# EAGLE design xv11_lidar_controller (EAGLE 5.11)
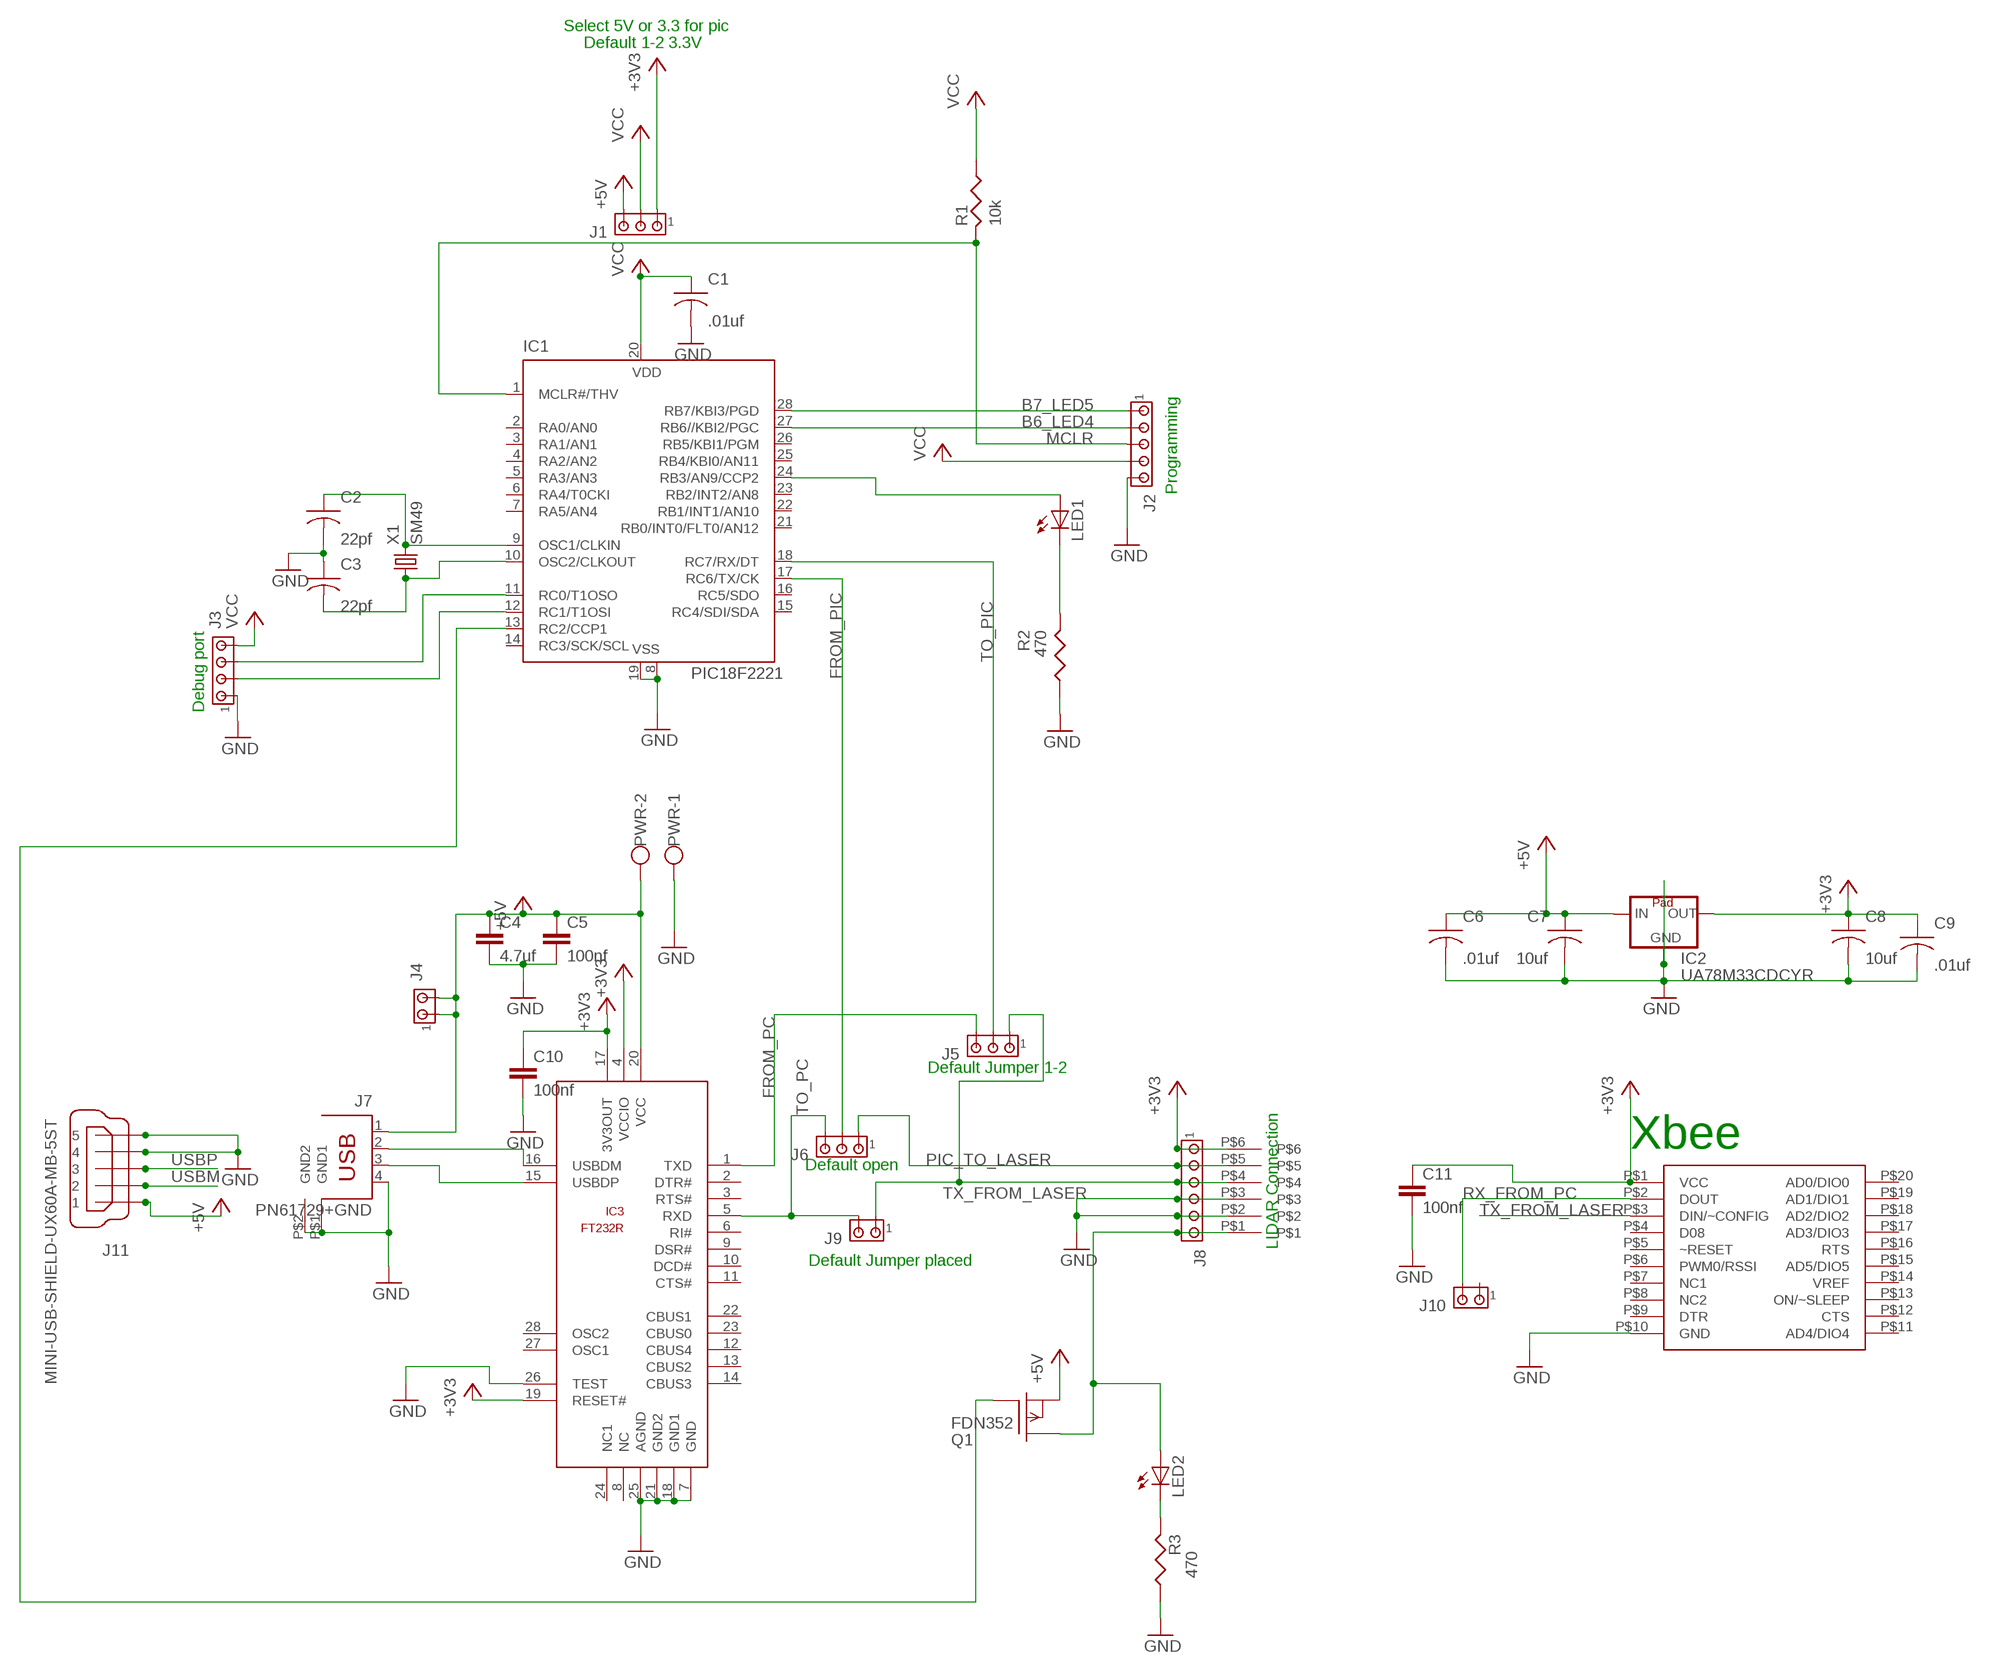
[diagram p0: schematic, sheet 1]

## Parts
C1  .01uf  C805  [C0805]
C2  22pf  C805  [C0805]
C3  22pf  C805  [C0805]
C4  4.7uf  C_805  [C0805]
C5  100nf  C_805  [C0805]
C6  .01uf  C805  [C0805]
C7  10uf  C805  [C0805]
C8  10uf  C805  [C0805]
C9  .01uf  C805  [C0805]
C10  100nf  C_805  [C0805]
C11  100nf  C_805  [C0805]
IC1  PIC18F2221  [SO-28W]
IC2  UA78M33CDCYR  [SOT223]
IC3  FT232R  [SSOP28]
IC4  XBEE  [MAXSTREAMXBEE]
J1  MTA03-100  [10X03MTA]
J2  MTA05-100  [10X05MTA]
J3  MTA04-100  [10X04MTA]
J4  MTA02-100  [10X02MTA]
J5  MTA03-100  [10X03MTA]
J6  MTA03-100  [10X03MTA]
J7  PN61729+GND  [PN61729+GND]
J8  MTA06-100  [10X06MTA]
J9  MTA02-100  [10X02MTA]
J10  MTA02-100  [10X02MTA]
J11  MINI-USB-SHIELD-UX60A-MB-5ST  [UX60A-MB-5ST]
LED1  LEDCHIPLED_0805  [CHIPLED_0805]
LED2  LEDCHIPLED_0805  [CHIPLED_0805]
PWR  Vin  W237-02P  [W237-132]
Q1  FDN352  [SUPERSOT3]
R1  10k  R-805  [R0805]
R2  470  R-805  [R0805]
R3  470  R-805  [R0805]
U$1  HEADER_2MMX6  [HEADER_2MMX6]
X1  SM49  [SM49]

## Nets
+3V3: C8.1 C9.1 C10.1 C11.1 IC2.3(OUT) IC3.4(VCCIO) IC3.17(3V3OUT) IC3.19(RESET#) IC4.P$1(VCC) J1.1 J8.6 U$1.P$6
+5V: C4.1 C5.1 C6.1 C7.1 IC2.1(IN) IC3.20(VCC) J1.3 J4.1 J4.2 J7.1 J11.1 PWR.2 Q1.P$2(S)
B6_LED4: IC1.27(RB6//KBI2/PGC) J2.2
B7_LED5: IC1.28(RB7/KBI3/PGD) J2.1
FROM_PC: IC3.1(TXD) J5.3
FROM_PIC: IC1.17(RC6/TX/CK) J6.2
GND: C1.2 C2.2 C3.1 C4.2 C5.2 C6.2 C7.2 C8.2 C9.2 C10.2 C11.2 IC1.8(VSS) IC1.19(VSS) IC2.2(GND) IC2.4(TAB) IC3.7(GND) IC3.18(GND1) IC3.21(GND2) IC3.25(AGND) IC3.26(TEST) IC4.P$10(GND) J2.5 J3.1 J7.4 J7.P$1(GND1) J7.P$2(GND2) J8.2 J8.3 J11.4 J11.5 PWR.1 R2.1 R3.1 U$1.P$2 U$1.P$3
MCLR: IC1.1(MCLR#/THV) J2.3 R1.2
N$1: IC1.24(RB3/AN9/CCP2) LED1.A
N$2: J8.1 LED2.A Q1.P$3(D) U$1.P$1
N$3: IC1.13(RC2/CCP1) Q1.P$1(G)
N$6: LED1.C R2.2
N$7: LED2.C R3.2
N$9: IC1.12(RC1/T1OSI) J3.2
N$10: IC1.11(RC0/T1OSO) J3.3
OSC: C2.1 IC1.9(OSC1/CLKIN) X1.2
OSC2: C3.2 IC1.10(OSC2/CLKOUT) X1.1
PIC_TO_LASER: J6.1 J8.5 U$1.P$5
RX_FROM_PC: IC4.P$2(DOUT) J10.2
TO_PC: IC3.5(RXD) J6.3 J9.2
TO_PIC: IC1.18(RC7/RX/DT) J5.2
TX_FROM_LASER: IC4.P$3(DIN/~CONFIG) J5.1 J8.4 J9.1 U$1.P$4
USBM: IC3.16(USBDM) J7.2 J11.2
USBP: IC3.15(USBDP) J7.3 J11.3
VCC: C1.1 IC1.20(VDD) J1.2 J2.4 J3.4 R1.1
Unconnected: IC1.2(RA0/AN0) IC1.3(RA1/AN1) IC1.4(RA2/AN2) IC1.5(RA3/AN3) IC1.6(RA4/T0CKI) IC1.7(RA5/AN4) IC1.14(RC3/SCK/SCL) IC1.15(RC4/SDI/SDA) IC1.16(RC5/SDO) IC1.21(RB0/INT0/FLT0/AN12) IC1.22(RB1/INT1/AN10) IC1.23(RB2/INT2/AN8) IC1.25(RB4/KBI0/AN11) IC1.26(RB5/KBI1/PGM) IC3.2(DTR#) IC3.3(RTS#) IC3.6(RI#) IC3.8(NC) IC3.9(DSR#) IC3.10(DCD#) IC3.11(CTS#) IC3.12(CBUS4) IC3.13(CBUS2) IC3.14(CBUS3) IC3.22(CBUS1) IC3.23(CBUS0) IC3.24(NC1) IC3.27(OSC1) IC3.28(OSC2) IC4.P$4(D08) IC4.P$5(~RESET) IC4.P$6(PWM0/RSSI) IC4.P$7(NC1) IC4.P$8(NC2) IC4.P$9(DTR) IC4.P$11(AD4/DIO4) IC4.P$12(CTS) IC4.P$13(ON/~SLEEP) IC4.P$14(VREF) IC4.P$15(AD5/DIO5) IC4.P$16(RTS) IC4.P$17(AD3/DIO3) IC4.P$18(AD2/DIO2) IC4.P$19(AD1/DIO1) IC4.P$20(AD0/DIO0) J10.1 J11.M1(S1) J11.M2(S2) J11.M3(S3) J11.M4(S4)

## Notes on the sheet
- Select 5V or 3.3 for pic
- Default 1-2 3.3V
- Programming
- Debug port
- Default Jumper 1-2
- Xbee
- Default open
- LIDAR Connection
- Default Jumper placed

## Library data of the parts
C1-C3 C6-C9 = Ringo:C805: 805 Cap
C4 C5 C10 C11 = NCR:C_805
IC1 = microchip-2:PIC18F2221
IC2 = Ringo:UA78M33CDCYR
IC3 = NCR:FT232R
IC4 = xbee:XBEE
J1 J5 J6 = con-amp:MTA03-100: AMP connector; OC_FARNELL: unknown; OC_NEWARK: unknown
J2 = con-amp:MTA05-100: AMP connector
J3 = con-amp:MTA04-100: AMP connector; OC_FARNELL: unknown; OC_NEWARK: unknown
J4 J9 J10 = con-amp:MTA02-100: AMP connector
J7 = con-berg:PN61729+GND
J8 = con-amp:MTA06-100: AMP connector
J11 = con-hirose:MINI-USB-SHIELD-: MINI USB Connector Source: http://www.hirose.co.jp/cataloge_hp/e24000019.pdf
LED1 LED2 = led:LED: LED
PWR = con-wago-508:W237-02P: WAGO SREW CLAMP
Q1 = Ringo:FDN352
R1-R3 = Ringo:R-805: 805 Resistor
U$1 = Ringo:HEADER_2MMX6
X1 = Ringo:SM49: ECS-200-20-5P-TR

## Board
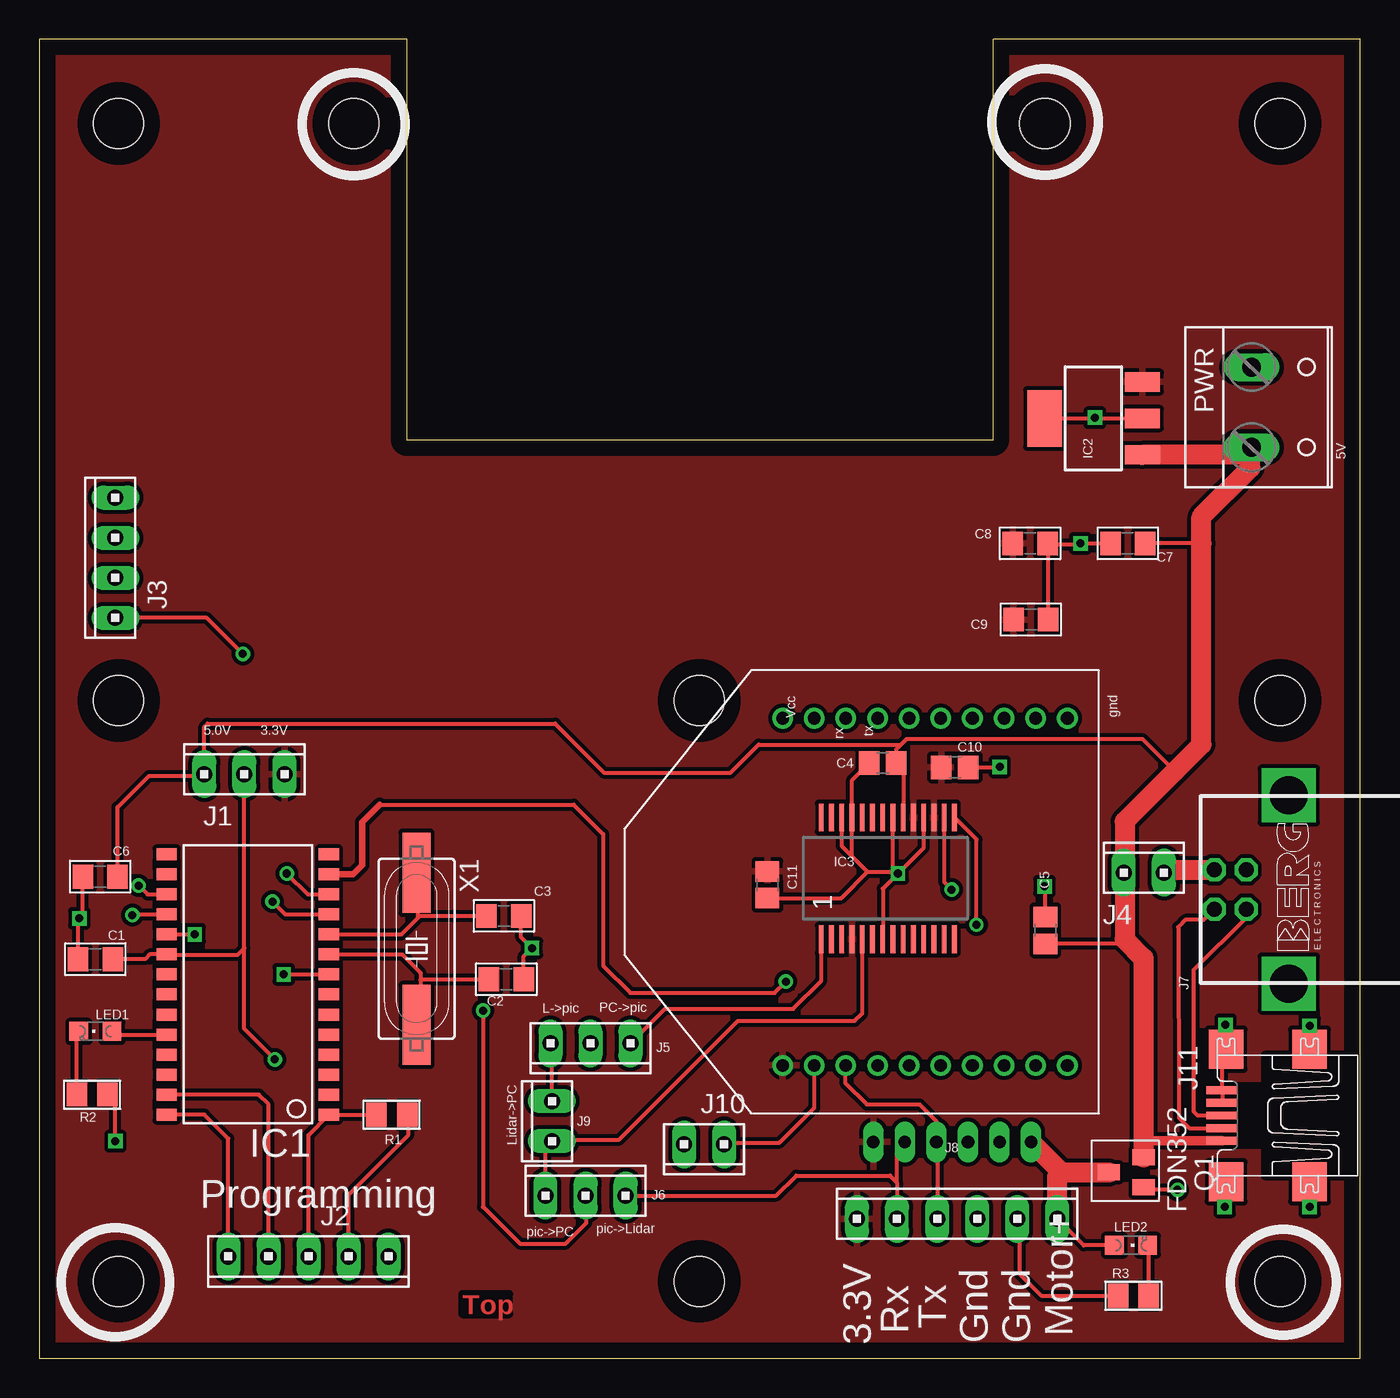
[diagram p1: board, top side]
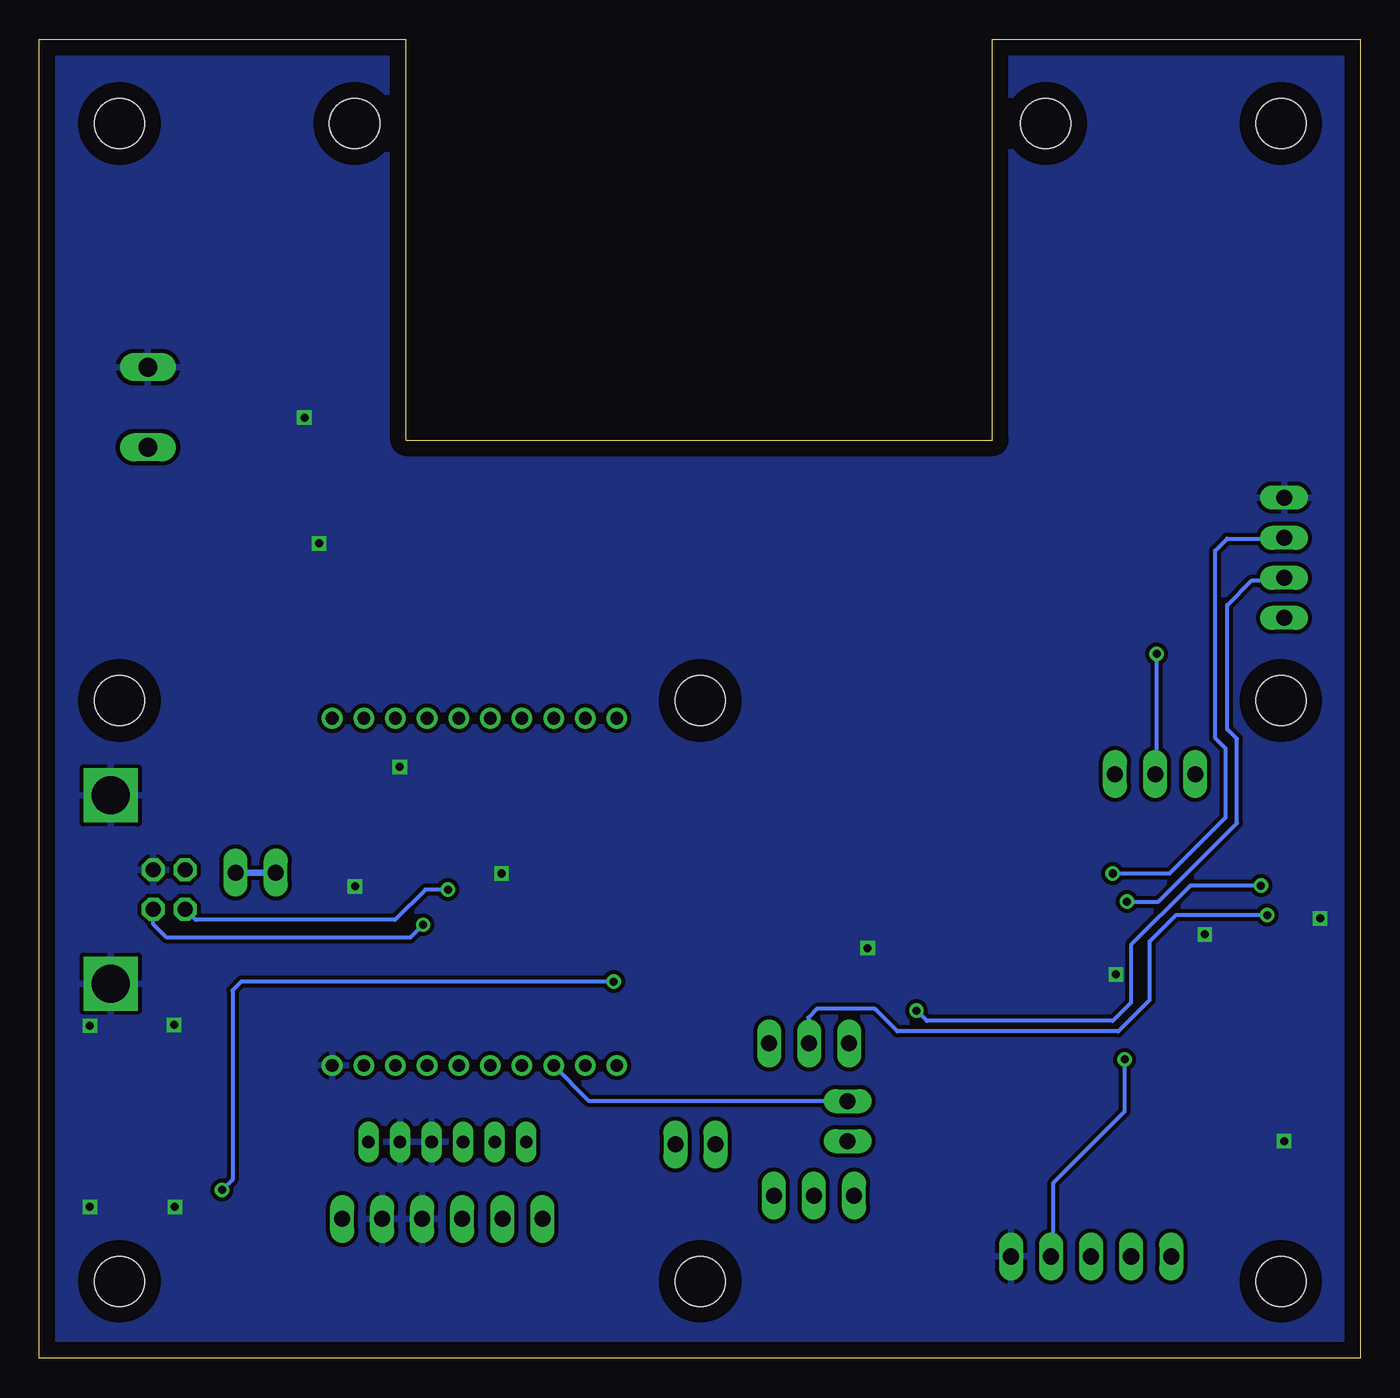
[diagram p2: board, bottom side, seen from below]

Size 83.76 x 83.63 mm. Coordinates in mm from the lower left corner, seen from the top.
Outline: 0,0 83.76,0 83.76,83.63 60.5,83.63 60.5,58.23 23.31,58.23 23.31,83.63 0,83.63 0,0
Copper layers (1+16): Top 0.035mm / dielectric 1.5mm / Bottom 0.035mm
Design rules "default *": minimum track width 8mil, minimum drill 15mil, track to track 8mil, track to pad 8mil, pad to pad 8mil, via to via 8mil, smd to smd 8mil, copper to edge 40mil, drill to drill 8mil, minimum pad ring 10mil, minimum via ring 8mil, stop-mask expansion 4mil, vias tented up to drill 0mil, thermal gap 10mil
Holes 3.17 mm at 5.02,4.89 78.68,4.89 5.02,41.72 19.94,78.3 63.77,78.3 41.85,4.89 78.68,41.72 5.02,78.3 78.68,78.3 41.85,41.72

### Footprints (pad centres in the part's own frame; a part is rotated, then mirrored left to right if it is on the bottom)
C0805 = smd 1.3 x 1.5: 1 -1.104,0; 2 1.104,0
C0805' = smd 1.3 x 1.5: 1 -0.85,0; 2 0.85,0
SO-28W = smd 0.762 x 1.27: 1 -7.62,-5.207; 2 -6.35,-5.207; 3 -5.08,-5.207; 4 -3.81,-5.207; 5 -2.54,-5.207; 6 -1.27,-5.207; 7 0,-5.207; 8 1.27,-5.207; 9 2.54,-5.207; 10 3.81,-5.207; 11 5.08,-5.207; 12 6.35,-5.207; 13 7.62,-5.207; 14 8.89,-5.207; 15 8.89,5.08; 16 7.62,5.08; 17 6.35,5.08; 18 5.08,5.08; 19 3.81,5.08; 20 2.54,5.08; 21 1.27,5.08; 22 0,5.08; 23 -1.27,5.08; 24 -2.54,5.08; 25 -3.81,5.08; 26 -5.08,5.08; 27 -6.35,5.08; 28 -7.62,5.08
SOT223 = smd 1.219 x 2.235: 1 -2.311,-3.099; 2 0,-3.099; 3 2.311,-3.099 | smd 3.6 x 2.2: 4 0,3.099
SSOP28 = smd 0.3 x 1.75: 1 -3.745,-3.865; 2 -3.095,-3.865; 3 -2.445,-3.865; 4 -1.795,-3.865; 5 -1.145,-3.865; 6 -0.495,-3.865; 7 0.155,-3.865; 8 0.805,-3.865; 9 1.455,-3.865; 10 2.105,-3.865; 11 2.755,-3.865; 12 3.405,-3.865; 13 4.055,-3.865; 14 4.705,-3.865; 15 4.705,3.865; 16 4.055,3.865; 17 3.405,3.855; 18 2.755,3.855; 19 2.105,3.855; 20 1.455,3.865; 21 0.805,3.865; 22 0.155,3.865; 23 -0.495,3.865; 24 -1.145,3.865; 25 -1.795,3.855; 26 -2.445,3.855; 27 -3.095,3.855; 28 -3.755,3.855
MAXSTREAMXBEE = drill 0.8 round: P$1 -11,8.026; P$2 -11,6.02; P$3 -11,4.013; P$4 -11,2.007; P$5 -11,0; P$6 -11,-2.007; P$7 -11,-4.013; P$8 -11,-6.02; P$9 -11,-8.026; P$10 -11,-10.033; P$11 11.01,-10.033; P$12 11.01,-8.026; P$13 11.01,-6.02; P$14 11.01,-4.013; P$15 11.01,-2.007; P$16 11.01,0; P$17 11.01,2.007; P$18 11.01,4.013; P$19 11.01,6.02; P$20 11.01,8.026
10X03MTA = drill 1.016 long: 1 2.54,0; 2 0,0; 3 -2.54,0
10X05MTA = drill 1.016 long: 1 5.08,0; 2 2.54,0; 3 0,0; 4 -2.54,0; 5 -5.08,0
10X04MTA = drill 1.016 long: 1 3.81,0; 2 1.27,0; 3 -1.27,0; 4 -3.81,0
10X02MTA = drill 1.016 long: 1 1.27,0; 2 -1.27,0
PN61729+GND = drill 0.95 octagon: 1 1.25,7.25; 2 -1.25,7.25; 3 -1.25,5.25; 4 1.25,5.25 | drill 2.413 square: P$1 -5.969,2.54; P$2 5.969,2.54
10X06MTA = drill 1.016 long: 1 6.35,0; 2 3.81,0; 3 1.27,0; 4 -1.27,0; 5 -3.81,0; 6 -6.35,0
UX60A-MB-5ST = smd 2 x 0.5: 1 2.25,1.6; 2 2.25,0.8; 3 2.25,0; 4 2.25,-0.8; 5 2.25,-1.6 | smd 2.2 x 2.5: M1 -3.3,-4.2; M2 -3.3,4.2; M3 2,4.2; M4 2,-4.2
CHIPLED_0805 = smd 1.2 x 1.2: A 0,-1.05; C 0,1.05
W237-132 = drill 1.194 long: 1 -2.54,-0.635; 2 2.54,-0.635
SUPERSOT3 = smd 1 x 1.4: P$1 -0.95,-1.1; P$2 0.95,-1.1; P$3 0,1.1
R0805 = smd 1.3 x 1.5: 1 -0.977,0; 2 0.977,0
HEADER_2MMX6 = drill 0.8 long: P$1 -6,0; P$2 -4,0; P$3 -2,0; P$4 0,0; P$5 2,0; P$6 4,0
SM49 = smd 5.08 x 1.778: 1 -4.826,0; 2 4.826,0

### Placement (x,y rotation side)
C1  3.55,25.31 180 top
C2  29.61,24.04 0 top
C3  29.46,28.05 180 top
C4  4.7uf  [C0805']  53.49,37.76 180 top
C5  100nf  [C0805']  63.8,27.14 90 top
C6  3.86,30.54 180 top
C7  69.03,51.68 180 top
C8  62.83,51.68 0 top
C9  62.89,46.85 0 top
C10  100nf  [C0805']  58.06,37.48 0 top
C11  100nf  [C0805']  46.17,30.04 270 top
IC1  13.15,23.08 90 top
IC2  66.85,59.6 90 top
IC3  53.34,30.44 0 top
IC4  55.16,29.58 90 top
J1  13,37.05 0 top
J2  17.06,6.46 180 top
J3  4.82,50.76 90 top
J4  70.05,30.8 0 top
J5  34.95,19.98 180 top
J6  34.64,10.33 0 top
J7  81.78,29.73 90 top
J8  58.21,8.85 0 top
J9  32.51,15.05 90 top
J10  42.16,13.58 180 top
J11  77.26,15.41 180 top
LED1  3.55,20.74 90 top
LED2  69.24,7.18 270 top
PWR  77.52,60.31 270 top
Q1  68.93,11.8 90 top
R1  22.35,15.46 180 top
R2  3.35,16.73 180 top
R3  69.39,3.98 0 top
U$1  56.89,13.73 180 top
X1  23.92,25.97 270 top

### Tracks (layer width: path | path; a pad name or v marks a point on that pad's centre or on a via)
+3V3
  pour Top (isolate 0.254): -0.06,83.32 83.81,83.58 83.71,0.47 -0.16,0.22
+5V
  Top 0.254: C6.1 4.96,34.95 6.95,36.94 10.36,36.94 J1.3 10.46,40.04 10.66,40.25 32.71,40.25 35.81,37.15 43.84,37.15 45.61,38.93 54.66,38.93 | IC3.20 54.79,37.3 C4.1 54.34,38.61 54.66,38.93 | 72,37.22 69.95,39.28 55.01,39.28 54.66,38.93 | C5.1 68.54,26.29 68.83,26.58 | 73.71,51.68 C7.1
  Top 0.61: J11.1 70.26,13.81 70.03,13.58
  Top 1.27: Q1.P$2 70.03,13.58 70.03,25.38 68.83,26.58 68.83,30.75 J4.2 68.83,30.85 68.83,34.05 72,37.22 73.71,38.93 73.71,51.68 73.71,53.35 76.8,56.45 76.8,57.7 PWR.2 76.4,57.29 IC2.1 | J7.1 71.5,30.98 J4.1
  Bottom 0.406: J4.2 J4.1
B6_LED4
  Top 0.254: J2.2 14.52,16.12 13.91,16.73 IC1.27
B7_LED5
  Top 0.254: J2.1 11.98,13.93 10.46,15.46 IC1.28
FROM_PC
  Top 0.254: IC3.1 49.59,23.95 47.8,22.16 39.67,22.16 J5.3
FROM_PIC  (via drill 0.51)
  Top 0.254: IC1.17 6.85,29.43 v6.29,29.98 | v28.14,22.06 28.14,9.61 30.48,7.28 33.37,7.28 34.69,8.6 34.69,10.27 J6.2
  Bottom 0.254: v6.29,29.98 10.76,29.98 14.52,26.23 14.52,22.57 15.69,21.4 27.48,21.4 v28.14,22.06
GND  (via drill 0.51)
  Top 0.254: v4.82,13.78 4.82,16.23 R2.1 | C2.2 30.72,25.5 v31.24,26.02 30.56,26.7 C3.1 | IC2.2 67,59.6 v66.95,59.65 66.9,59.6 IC2.4 | v15.49,24.35 IC1.8 | IC1.19 v9.85,26.89 | C1.2 2.45,27.81 v2.54,27.9 2.75,28.12 C6.2 | IC3.7 53.49,29.78 v54.45,30.75 | IC3.21 54.14,31.06 v54.45,30.75 | IC3.18 56.09,32.38 v54.45,30.75 | 51.54,31.83 IC3.25 51.54,36.66 C4.2 | 52.52,30.85 51.54,31.83 | 52.52,30.85 54.35,30.85 v54.45,30.75 | IC3.26 50.89,32.48 51.54,31.83 | C5.2 63.8,29.88 v63.75,29.93 | C11.2 50.86,29.19 52.52,30.85 | C9.2 63.99,51.63 | 63.99,51.63 C8.2 | 63.99,51.63 65.98,51.63 v66.04,51.68 C7.2 | C10.2 60.88,37.48 v60.9,37.5 | R3.1 63.55,3.98 62.17,5.35 62.17,8.7 J8.2 | J11.4 J11.5 75.01,20.93 v75.23,21.15
  other vias: 80.56,21.09 75.18,9.61 80.56,9.61
  pour Bottom (isolate 0.254): -0.11,83.63 83.87,83.53 83.71,0.47 -0.26,0.57
MCLR
  Top 0.254: J2.3 17.06,14.16 IC1.1 R1.2
N$1
  Top 0.254: IC1.24 4.8,20.54 LED1.A
N$2
  Top 0.254: LED2.A 66.24,7.18 J8.1
  Top 1.27: 64.82,11.8 Q1.P$3 | 64.82,11.8 U$1.P$1 | J8.1 64.56,11.54 64.82,11.8
N$3  (via drill 0.51)
  Top 0.254: 21.59,35.12 33.88,35.12 35.76,33.24 35.76,24.9 37.49,23.18 46.63,23.18 v47.34,23.89 | 70.25,10.63 Q1.P$1 70.2,10.68 v72.18,10.68
  Top 0.406: IC1.13 19.91,30.7 20.47,31.25 20.47,34 21.59,35.12
  Bottom 0.254: v47.34,23.89 70.96,23.89 71.52,23.33 71.52,11.34 v72.18,10.68
N$6
  Top 0.254: R2.2 2.37,20.61 LED1.C
N$7
  Top 0.254: R3.2 70.37,7.1 LED2.C
N$9  (via drill 0.51)
  Top 0.254: IC1.12 17.01,29.43 v15.69,30.75
  Bottom 0.254: v15.69,30.75 12.09,30.75 8.53,34.3 8.53,38.67 9.19,39.33 9.19,51.22 8.43,51.98 4.87,51.98 J3.2
N$10  (via drill 0.51)
  Top 0.254: IC1.11 15.59,28.16 v14.78,28.97
  Bottom 0.254: v14.78,28.97 12.8,28.97 7.82,33.95 7.82,39.28 8.43,39.89 8.43,47.76 6.85,49.34 4.97,49.34 J3.3
OSC
  Top 0.254: IC1.9 23.01,25.62 24.18,24.45 24.18,23.99 | 24.18,23.99 24.18,21.4 X1.2 | C2.1 24.23,24.04 24.18,23.99
OSC2
  Top 0.254: IC1.10 22.96,26.89 24.02,27.95 | 24.02,27.95 24.02,30.7 X1.1 | C3.2 24.13,28.05 24.02,27.95
PIC_TO_LASER
  Top 0.254: 54.4,11.14 J8.5 | 54.4,11.14 54.4,13.24 U$1.P$5 | J6.1 46.73,10.33 48,11.6 53.94,11.6 54.4,11.14
RX_FROM_PC
  Top 0.254: IC4.P$2 49.14,15.89 46.93,13.68 43.53,13.68 J10.2
TO_PC
  Top 0.254: IC3.5 52.19,21.88 51.71,21.4 44.29,21.4 36.77,13.88 32.61,13.88 J9.2 32.1,13.37 J6.3
TO_PIC  (via drill 0.51)
  Top 0.254: IC1.18 5.94,28.16 v5.89,28.11
  Bottom 0.254: v5.89,28.11 11.68,28.11 13.36,26.43 13.36,22.72 15.34,20.74 29.36,20.74 30.78,22.16 34.44,22.16 35,21.6 35,20.03 J5.2
TX_FROM_LASER
  Top 0.254: J8.4 56.94,13.68 U$1.P$4 56.89,15.05 55.82,16.12 52.47,16.12 51.1,17.49 51.1,18.53 IC4.P$3 | J9.1 32.51,19.88 J5.1
  Bottom 0.254: J9.1 48.89,16.32 IC4.P$3
USBM  (via drill 0.51)
  Top 0.254: IC3.16 57.39,30.2 v57.86,29.73 | J7.2 73.85,27.8 72.69,27.8 72.23,27.34 72.28,15.76 72.28,15.25 72.93,14.61 J11.2
  Bottom 0.254: v57.86,29.73 59.28,29.73 61.21,27.8 73.85,27.8 J7.2
USBP  (via drill 0.51)
  Top 0.254: v59.43,27.5 59.43,32.92 IC3.15 | J11.3 73.45,15.41 73.2,15.66 73.2,24.62 76.53,27.95 J7.3
  Bottom 0.254: J7.3 76.53,27.53 75.69,26.68 60.24,26.68 v59.43,27.5
VCC  (via drill 0.51)
  Top 0.254: 13,26.02 J1.2 | 13,26.02 12.54,25.57 8.12,25.57 IC1.20 7.01,25.62 6.7,25.31 C1.1 | J2.4 19.6,10.38 23.41,14.19 23.41,15.37 R1.1 | 13,26.02 13,20.89 v14.93,18.96 | J3.4 10.61,46.95 v12.9,44.67
  Bottom 0.254: v14.93,18.96 14.93,15.66 19.45,11.14 19.45,6.62 J2.4 | v12.9,44.67 12.9,37.15 J1.2

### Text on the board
Top: Top
tPlace: 5V | Vcc | gnd | tx | rx
tNames: 5.0V | 3.3V | L->pic | PC->pic | Lidar->PC | Programming | pic->PC | pic->Lidar | Rx | Tx | Motor+ | 3.3V | Gnd | Gnd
